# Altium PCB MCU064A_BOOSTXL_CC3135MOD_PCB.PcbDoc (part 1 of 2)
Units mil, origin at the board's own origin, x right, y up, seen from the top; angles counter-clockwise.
Board outline 2300 x 1700 mil, 2 copper layers (Top Layer, Bottom Layer), stack 45.707 mil thick; 110 components, 81 nets, 379 pads, 305 vias.
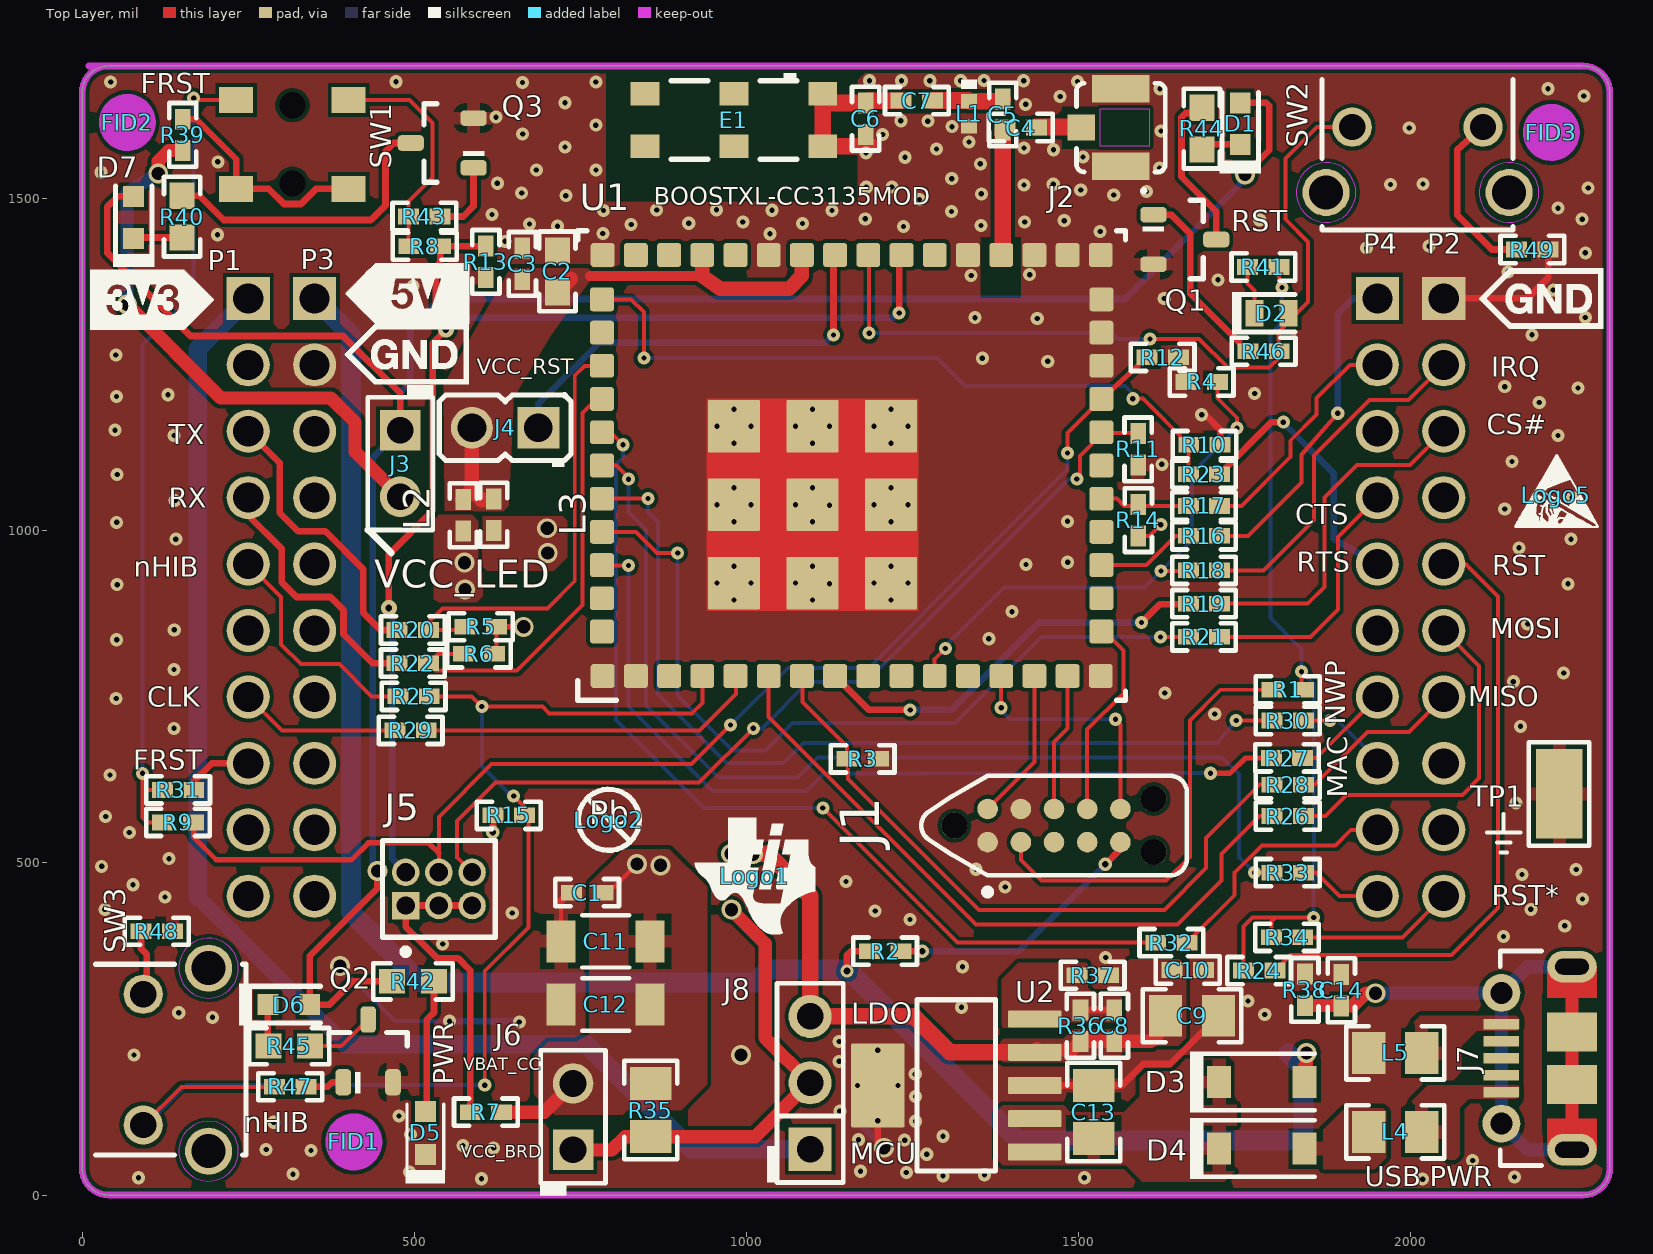
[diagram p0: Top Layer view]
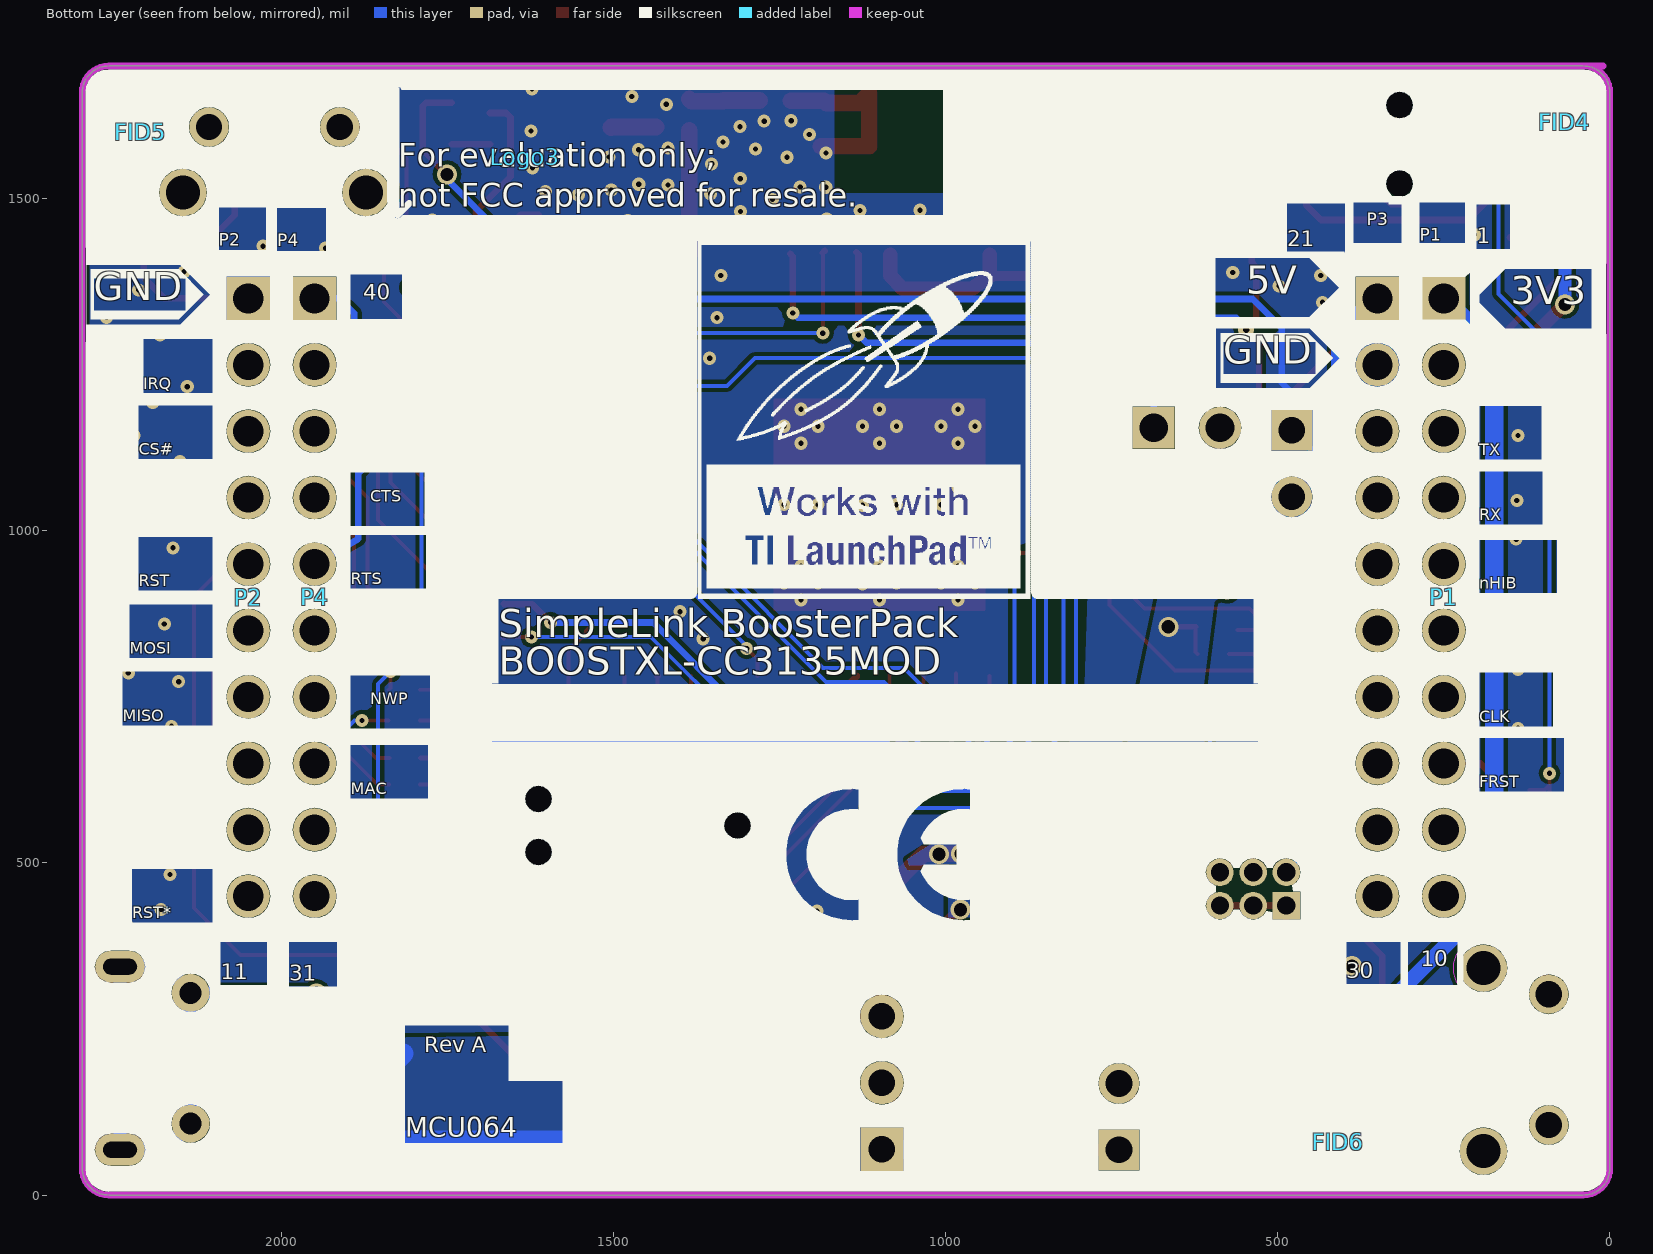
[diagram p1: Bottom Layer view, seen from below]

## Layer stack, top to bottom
Top Solder: solder mask 0.6, Solder Resist, Dk 3.5
Top Layer: signal copper 1.8
Dielectric1: core 42.107, FR-4, Dk 4.8
Bottom Layer: signal copper 1.8
Bottom Solder: solder mask 0.6, Solder Resist, Dk 3.5

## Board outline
0,40 ccw(c40,40) 40,0 2260,0 ccw(c2260,40) 2300,40 2300,1660 ccw(c2260,1660) 2260,1700 40,1700 ccw(c40,1660) 0,1660

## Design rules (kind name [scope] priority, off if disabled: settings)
AcuteAngle [All] p1: minimum=4.50000000000000E+0001 checktracksonly=TRUE
AssemblyTestPointUsage [All] p1: valid=2
Clearance Clearance_8 [InNamedPolygon('NONET_L01_P126')] p1: gap=0 ignorepadtopadclearanceinfootprint=FALSE
Clearance Clearance_7 [InNamedPolygon('NONET_L01_P124')] p2: gap=0 ignorepadtopadclearanceinfootprint=FALSE
Clearance Clearance_6 [InNamedPolygon('NONET_L01_P129')] p3: gap=0 ignorepadtopadclearanceinfootprint=FALSE
Clearance Clearance_5 [InNamedPolygon('NONET_L01_P125')] p4: gap=0 ignorepadtopadclearanceinfootprint=FALSE
Clearance [InNamedPolygon('NONET_L01_P125')] p5: gap=10 ignorepadtopadclearanceinfootprint=FALSE except(0: Arc-Hole Track-Hole SMDPad-Hole THPad-Hole Via-Hole Fill-Hole Poly-Hole Region-Hole Text-Hole)
Clearance Clearance_4 [All] p6: gap=6 ignorepadtopadclearanceinfootprint=FALSE except(0: Arc-Hole Track-Hole SMDPad-Hole THPad-Hole Via-Hole Fill-Hole Poly-Hole Region-Hole Text-Hole)
Clearance Clearance_3 [InNetClass('50 ohm') vs INPOLY] p7: gap=15 ignorepadtopadclearanceinfootprint=FALSE except(0: Arc-Hole Track-Hole SMDPad-Hole THPad-Hole Via-Hole Fill-Hole Poly-Hole Region-Hole Text-Hole)
Clearance Clearance_1 [inpoly vs inpoly] p8: gap=10 ignorepadtopadclearanceinfootprint=FALSE except(0: Arc-Hole Track-Hole SMDPad-Hole THPad-Hole Via-Hole Fill-Hole Poly-Hole Region-Hole Text-Hole)
Clearance Clearance_Poly [InPolygon] p9: gap=8 ignorepadtopadclearanceinfootprint=FALSE except(0: Arc-Hole Track-Hole SMDPad-Hole THPad-Hole Via-Hole Fill-Hole Poly-Hole Region-Hole Text-Hole)
Clearance Clearance_2 [iskeepout] p10: gap=0 ignorepadtopadclearanceinfootprint=FALSE
Clearance Clearance_RF [InNet('NetC5_1') vs InNet('RF_BG')] p11: gap=6 ignorepadtopadclearanceinfootprint=FALSE except(0: Arc-Hole Track-Hole SMDPad-Hole THPad-Hole Via-Hole Fill-Hole Poly-Hole Region-Hole Text-Hole; 6.5: Track-Poly)
Clearance Clearance_RF_1 [InNet('NetC6_2') vs InNet('RF_BG')] p12: gap=6 ignorepadtopadclearanceinfootprint=FALSE except(0: Arc-Hole Track-Hole SMDPad-Hole THPad-Hole Via-Hole Fill-Hole Poly-Hole Region-Hole Text-Hole; 6.5: Track-Poly)
ComponentClearance ComponentClearance_MountingHoles_FiducialMarks [InComponentClass('Mounting Holes') vs InComponentClass('FiducialMark')] p1: gap=10 collisioncheckmode=3 verticalgap=10 showdistances=FALSE
ComponentClearance ComponentClearance_Shunt [InComponentClass('Header') vs InComponentClass('Shunt')] p2: gap=0 collisioncheckmode=3 verticalgap=0 showdistances=FALSE
ComponentClearance ComponentClearance_Logo [InComponentClass('Logo')] p3: gap=0 collisioncheckmode=3 verticalgap=0 showdistances=FALSE
ComponentClearance ComponentClearance_ScrewToNut [(HasFootprint('NY PMS 440 0025 PH')) vs (HasFootprint('Keystone_1902C'))] p4: gap=0 collisioncheckmode=3 verticalgap=0 showdistances=FALSE
ComponentClearance ComponentClearance_MountingHoles [InComponentClass('Mounting Holes')] p5: gap=20 collisioncheckmode=3 verticalgap=100000 showdistances=FALSE
ComponentClearance ComponentClearance_SmallPassives [HasFootprint('0201*') or HasFootprint('0402*') or HasFootprint('0508') or HasFootprint('0603*') or HasFootprint('0612') or HasFootprint('0805*') or HasFootprint('0815*') or HasFootprint('0830*') or HasFootprint('1206*') or HasFootprint('1210*') or HasFootprint('1808*') or HasFootprint('1812*') or HasFootprint('1825*') or HasFootprint('2010*') or HasFootprint('2220*') or HasFootprint('2225*') or HasFootprint('2512*') or HasFootprint('2728*') or HasFootprint('3518*') vs HasFootprint('0201*') or HasFootprint('0402*') or HasFootprint('0508') or HasFootprint('0603*') or HasFootprint('0612') or HasFootprint('0805*') or HasFootprint('0815*') or HasFootprint('0830*') or HasFootprint('1206*') or HasFootprint('1210*') or HasFootprint('1808*') or HasFootprint('1812*') or HasFootprint('1825*') or HasFootprint('2010*') or HasFootprint('2220*') or HasFootprint('2225*') or HasFootprint('2512*') or HasFootprint('2728*') or HasFootprint('3518*')] p6: gap=10 collisioncheckmode=3 verticalgap=10 showdistances=FALSE
ComponentClearance ComponentClearance_THtoSMT [IsThruComponent vs IsSMTComponent] p7: gap=10 collisioncheckmode=3 verticalgap=10 showdistances=FALSE
ComponentClearance ComponentClearance_THtoTH [IsThruComponent vs IsThruComponent] p8: gap=0 collisioncheckmode=3 verticalgap=10 showdistances=FALSE
ComponentClearance [All] p9: gap=10 collisioncheckmode=3 verticalgap=10 showdistances=FALSE
DiffPairsRouting [All] p1: maxlimit=100 minlimit=10 mostfreqgap=10 toplayer_minwidth=15 toplayer_maxwidth=15 toplayer_prefwidth=15 bottomlayer_minwidth=15 bottomlayer_maxwidth=15 bottomlayer_prefwidth=15 maxuncoupledlength=1000
FabricationTestPointUsage TestPointUsage [All] p1: valid=2 allowmultiple=FALSE
FabricationTestpoint Testpoint [All] p1: side=3 testpointundercomponent=TRUE minsize=40 maxsize=100 preferedsize=60 minholesize=0 maxholesize=40 preferedholesize=32 testpointgrid=1 allowsidetop=TRUE allowsidebottom=TRUE usegrid=TRUE gridtolerance=0.01
FanoutControl Fanout_LCC [IsLCC] p1: bgadir=Out bgaviamode=Centered fanoutstyle=Auto fanoutdirection=Alternating viagrid=1 // Fanout_LCC (Default Rule)
FanoutControl Fanout_BGA [IsBGA] p2: bgadir=Out bgaviamode=Centered fanoutstyle=Auto fanoutdirection=Alternating viagrid=1 // Fanout_BGA (Default Rule)
FanoutControl Fanout_Default [All] p4: bgadir=Out bgaviamode=Centered fanoutstyle=Auto fanoutdirection=Alternating viagrid=1 // Fanout_Default (Default Rule)
FanoutControl Fanout_Small [(CompPinCount < 5)] p5: bgadir=Out bgaviamode=Centered fanoutstyle=Auto fanoutdirection=OutThenIn viagrid=1 // Fanout_Small (Default Rule)
Height [All] p1: minheight=0 maxheight=1345 prefheight=500
HoleSize [All] p1: absolutevalues=TRUE maxlimit=251 minlimit=7.86 maxpercent=80.000 minpercent=20.000
MinimumAnnularRing MinimumAnnularRing_ThermalPadVias [IsVia and InAnyComponent] p1: minimumring=5
MinimumAnnularRing [All] p2: minimumring=5
MinimumSolderMaskSliver MinimumSolderMaskSliver_Logo [InComponentClass('Logo') vs InComponentClass('Logo')] p1: minsoldermaskwidth=0.7
MinimumSolderMaskSliver [All] p2: minsoldermaskwidth=3
PlaneConnect [All] p1: planeconnectstyle=Relief reliefexpansion=10 reliefentries=4 reliefconductorwidth=10 reliefairgap=10
PolygonConnect PolygonConnect_3 [InPadClass('SMD')] p1: connectstyle=Relief reliefconductorwidth=20 reliefentries=4 polygonreliefangle="90 Angle" airgapwidth=10
PolygonConnect [InPadClass('TH')] p2: connectstyle=Relief reliefconductorwidth=20 reliefentries=4 polygonreliefangle="90 Angle" airgapwidth=10
PolygonConnect PolygonConnect_1 [InPadClass('PLANECLASS')] p3: connectstyle=Direct reliefconductorwidth=10 reliefentries=4 polygonreliefangle="90 Angle" airgapwidth=10
PolygonConnect PolygonConnect_2 [All] p4: connectstyle=Direct reliefconductorwidth=10 reliefentries=4 polygonreliefangle="90 Angle" airgapwidth=10
RoutingVias ThermalPadVias [IsVia and InAnyComponent] p1: holewidth=7.87 width=24 viastyle="Through Hole" minholewidth=7.87 minwidth=19 maxholewidth=12.99 maxwidth=24
RoutingVias [All] p2: holewidth=16 width=34 viastyle="Through Hole" minholewidth=7.87 minwidth=19 maxholewidth=40 maxwidth=65
SilkToSilkClearance SilkToSilkClearance_Pb-FreeLogo [(HasFootprint('Pb-Free_Overlay_Medium') OR HasFootprint('Pb-Free_Overlay_Small')) vs (HasFootprint('Pb-Free_Overlay_Medium') OR HasFootprint('Pb-Free_Overlay_Small'))] p1: silktosilkclearance=0
SilkToSilkClearance [All] p2: silktosilkclearance=3
SilkToSolderMaskClearance "Silk to Solder Mask Opening" [IsPad] p1: minsilkscreentomaskgap=1 clearancetoexposedcopper=TRUE
SolderMaskExpansion SolderMaskExpansion_1 [InPadClass('SM')] p1: expansion=2.5
SolderMaskExpansion [All] p2: expansion=0
Width [All] p1: maxlimit=40 minlimit=6 preferedwidth=6 checkconnectedcopper=TRUE
15 further rules are at their usual default settings.

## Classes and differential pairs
component class Logo: Logo1
net class Undefined: CC_SPI_CLK CC_SPI_CS CC_SPI_DIN CC_SPI_DOUT CC_UART1_TX GND NetC2_1 NetD4_2 NetJ4_1 SFL_CLK VBAT_CC VCC_LDO_3V3 VCC_LED
net class "50 ohm": NetC4_1 RF_BG
component class BOOSTXL_CC3135MOD_EVMHardware: FID1 FID2 FID3 FID4 FID5 FID6 Logo1 Logo2 Logo3 Logo5
pad class SM: J4-3 J4-4 J4-5 J4-6
component class BOOSTXL_CC3135MOD_HostInterface: C8 C9 C10 C11 C12 C13 C14 D1 D2 D3 D4 D5 D6 D7 J3 J6 J7 J8 L4 L5 P1 P2 P3 P4 Q1 Q2 Q3 R15 R16 R17 R18 R19 R20 R21 R22 R23 R24 R25 R26 R27 R28 R29 R30 R31 R32 R33 R34 R35 R36 R37 R38 R39 R40 R41 R42 R43 R44 R45 R46 R47 R48 R49 SW1 SW2 SW3 TP1 U2
component class BOOSTXL_CC3135MOD_Engine: C1 C2 C3 C4 C5 C6 C7 E1 J1 J2 J4 J5 L1 L2 L3 R1 R2 R3 R4 R5 R6 R7 R8 R9 R10 R11 R12 R13 R14 U1
component class FiducialMark: FID1 FID2 FID3 FID4 FID5 FID6
component class Header: J3 J4 J5 J6 J8
pad class PLANECLASS: J2-1 J2-2 J2-3
pad class SMD: C11-1 C11-2 C13-1 C13-2 C18-1 C18-2 C28-1 C28-2 C29-1 C29-2 C30-1 C30-2 C31-1 C31-2 C32-1 C32-2 D3-1 D3-2 D4-1 D4-2 L7-1 L7-2 L8-1 L8-2 Q1-1 Q1-2 Q1-3 Q2-1 Q2-2 Q2-3 Q3-1 Q3-2 Q3-3 R2-1 R2-2 R5-1 R5-2 R8-1 R8-2 R10-1 R10-2 R11-1 R11-2 R13-1 R13-2 R14-1 R14-2 R15-1 R15-2 R16-1 R16-2 R17-1 R17-2 R18-1 R18-2 R20-1 R20-2 R21-1 R21-2 R22-1 R22-2 R23-1 R23-2 R24-1 R24-2 R25-1 R25-2 R26-1 R26-2 R29-1 R29-2 R31-1 R31-2 R32-1 R32-2 R33-1 R33-2 R39-1 R39-2 R40-1 R40-2 R41-1 R41-2 R42-1 R42-2 R43-1 R43-2 R45-1 R45-2 R46-1 R46-2 R48-1 R48-2 R54-1 R54-2 R56-1 R56-2 R57-1 R57-2 R59-1 R59-2 R60-1 R60-2 R290-1 R290-2 R295-1 R295-2 R297-1 R297-2 TP1-1 U4-6

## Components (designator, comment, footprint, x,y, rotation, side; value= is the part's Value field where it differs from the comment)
C1 "GRM155R60J475ME47D" 0402 760.2,455.3 r180 top locked value=4.7uF
C2 "GRM188R60J106ME47D" 0603 715.5,1390.7 r90 top locked value=10uF
C3 "GRM155R60J104KA01D" 0402 662.7,1402.1 r90 top locked value=0.1uF
C4 "500R07S100JV4T" 0402 1413.1,1607.3 r180 top value=10pF
C5 "500R07S100JV4T" 0402 1386,1626.87 r90 top value=10pF
C6 "GRM1555C1H1R8CA01D" 0402 1179.6,1620.69 r270 top value=1.8pF
C7 "GJM1555C1H3R3BB01D" 0402 1256.62,1647.9 r0 top value=3.3pF
C8 "GRM1555C1H150JA01D" 0402 1554,255 r90 top locked value=15pF
C9 "GRM21BR61A106KE19L" 0805_HV 1671,270 r0 top locked value=10uF
C10 "GRM155R60J104KA01D" 0402 1664.5,338.8 r0 top value=0.1uF
C11 "GRM31CR60J107ME39L" 1206_180 788,382 r180 top locked value=100uF
C12 "GRM31CR60J107ME39L" 1206_180 788,287 r180 top locked value=100uF
C13 "GRM21BR61A106KE19L" 0805_HV 1523,125 r90 top locked value=10uF
C14 "GRM155R71H102KA01D" 0402 1895.8,308.3 r90 top locked value=1000pF
D1 "150060YS75000" WL-SMCW_YELLOW 1743.6,1613 r90 top locked value=Yellow
D2 "CD0603-B00340" Diode_0603 1790.51,1327.6 r0 top locked value=45V
D3 "MBR130T1G" SOD-123 1776,170 r0 top locked value=30V
D4 "MBR130T1G" SOD-123 1776,70 r0 top locked value=30V
D5 "SML-311UTT86" SML-31_Red 516.6,93.5 r90 top locked value=Red
D6 "150060GS75000" WL-SMCW_GREEN 311.1,286.8 r0 top locked value=Green
D7 "150060RS75000" WL-SMCW_RED 77.5,1472 r90 top locked value=Red
E1 "M830520" Ethertronics_M830520 981.3,1618.52 r270 top locked
FID1 "Fiducial" Fiducial6.4-20 409,80 r90 top locked
FID2 "Fiducial" Fiducial6.4-20 68,1615 r90 top locked
FID3 "Fiducial" Fiducial6.4-20 2212,1600 r90 top locked
FID4 "Fiducial" Fiducial6.4-20 68,1615 r90 bottom locked
FID5 "Fiducial" Fiducial6.4-20 2212,1600 r90 bottom
FID6 "Fiducial" Fiducial6.4-20 409,80 r90 bottom locked
J1 "TC2050-IDC-430-FP" Tag_TC2050-NL 1463.2,556.3 r90 top locked
J2 "U.FL-R-SMT-1" CONN_UFL-R-SMT-1 1563.9,1607.3 r0 top locked
J3 "HMTSW-102-07-G-S-240" SAMTEC_HMTSW-102-07-G-S-240 478.8,1101.3 r270 top locked
J4 "961102-6404-AR" 3M_961102-6404-AR 636.8,1155.2 r180 top locked
J5 "GRPB032VWVN-RC" Sullins_GRPB032VWVN-RC 537,460.9 r90 top locked
J6 "HMTSW-102-07-G-S-240" SAMTEC_HMTSW-102-07-G-S-240 739,118 r90 top locked
J7 "105017-0001" CONN_105017-0001 2189.93,206 r90 top locked
J8 "TSW-103-07-G-S" TSW-103-07-G-S 1096,169 r90 top locked
L1 "LQG15HS3N0S02D" IND_LQG15H 1335.3,1628.2 r270 top value=3nH
L2 "BLM15AX100SN1D" 0402 573.8,1023.5 r270 top locked value="10 ohm"
L3 "BLM15AX100SN1D" 0402 619.5,1024.3 r270 top locked value="10 ohm"
L4 "MMZ2012R300A" 0805_HV 1977,95 r180 top locked value="30 ohm"
L5 "MMZ2012R300A" 0805_HV 1977,214 r0 top locked value="30 ohm"
Logo1 "Texas Instruments" TI_Symbol_Overlay_Small 1012.9,480.1 r0 top
Logo2 "Pb-Free Symbol" Pb-Free_Overlay_Small 792.9,565 r0 top
Logo3 "FCC disclaimer" FCC_disclaimer 1633,1563 r180 bottom
Logo5 "ESD Susceptible" ESD_Overlay_Small 2219.1,1053.9 r0 top
P1 "SSW-110-23-F-S" CONN_SSW-110-23-F-S 250,900 r90 bottom locked
P2 "SSW-110-23-F-S" CONN_SSW-110-23-F-S 2050,900 r90 bottom locked
P3 "SSW-110-23-F-S" CONN_SSW-110-23-F-S 350,900 r90 bottom locked
P4 "SSW-110-23-F-S" CONN_SSW-110-23-F-S 1950,900 r90 bottom locked
Q1 "BSS138" SOT-23 1660.2,1438.7 r0 top locked value=50V
Q2 "BSS138" SOT-23 430.5,217.1 r90 top locked value=50V
Q3 "BSS138" SOT-23 542,1584 r180 top locked value=50V
R1 "ERJ-2GE0R00X" 0402 1815.1,760.8 r0 top locked value=0
R2 "ERJ-2GE0R00X" 0402 1209,367.2 r0 top locked value=0
R3 "CRCW0402100KJNED" 0402 1175,656.8 r0 top locked value=100k
R4 "CRCW0402100KJNED" 0402 1685.5,1224.2 r180 top locked value=100k
R5 "CRCW0402100KJNED" 0402 600,855.7 r180 top locked value=100k
R6 "CRCW0402100KJNED" 0402 597.3,814.9 r180 top locked value=100k
R7 "CRCW04021K00JNED" 0402 607.9,124.9 r180 top locked value=1.0k
R8 "ERJ-2GE0R00X" 0402 515.7,1428.6 r180 top locked value=0
R9 "ERJ-2GE0R00X" 0402 144.2,561 r180 top locked value=0
R10 "CRCW0402100KJNED" 0402 1689.7,1129.9 r0 top locked value=100k
R11 "CRCW0402100KJNED" 0402 1589.8,1122.8 r270 top locked value=100k
R12 "CRCW0402100KJNED" 0402 1626.8,1261.2 r0 top locked value=100k
R13 "CRCW0402100KJNED" 0402 607.7,1405.1 r270 top locked value=100k
R14 "CRCW0402100KJNED" 0402 1590.2,1016.1 r90 top locked value=100k
R15 "CRCW0402100KFKED" 0402 642.2,571.7 r180 top locked value=100k
R16 "ERJ-2GE0R00X" 0402 1689,992.5 r0 top locked value=0
R17 "ERJ-2GE0R00X" 0402 1689,1037.5 r0 top locked value=0
R18 "ERJ-2GE0R00X" 0402 1689,940.5 r180 top locked value=0
R19 "ERJ-2GE0R00X" 0402 1689,890.5 r180 top locked value=0
R20 "ERJ-2GE0R00X" 0402 497.9,850.8 r180 top locked value=0
R21 "ERJ-2GE0R00X" 0402 1689,840.5 r0 top locked value=0
R22 "ERJ-2GE0R00X" 0402 497.9,800.8 r180 top locked value=0
R23 "ERJ-2GE0R00X" 0402 1689,1085.5 r0 top locked value=0
R24 "ERJ-2GE0R00X" 0402 1772,338 r180 top locked value=0
R25 "CRCW04021K00JNED" 0402 498.9,750.8 r180 top locked value=1.0k
R26 "ERJ-2GE0R00X" 0402 1815.1,570.7 r180 top locked value=0
R27 "ERJ-2GE0R00X" 0402 1814,658 r0 top locked value=0
R28 "ERJ-2GE0R00X" 0402 1815.1,617.8 r180 top locked value=0
R29 "ERJ-2GE0R00X" 0402 494.4,699.7 r180 top locked value=0
R30 "ERJ-2GE0R00X" 0402 1815.1,714.5 r0 top locked value=0
R31 "CRCW04021K00JNED" 0402 144.38,610 r0 top locked value=1.0k
R32 "ERJ-2GE0R00X" 0402 1640,380 r0 top locked value=0
R33 "ERJ-2GE0R00X" 0402 1815.1,485.4 r0 top locked value=0
R34 "ERJ-2GE0R00X" 0402 1814,388 r180 top locked value=0
R35 "CRM0805-FX-R100ELF" 0805_HV 856,128 r90 top locked value=0.1
R36 "CRCW040251K0JNED" 0402 1503,255 r270 top locked value=51k
R37 "CRCW040230K1FKED" 0402 1521.29,330.95 r180 top locked value=30.1k
R38 "CRCW0402100KJNED" 0402 1841,309 r90 top locked value=100k
R39 "ERJ-2RKF1000X" 0402 151.4,1596.2 r270 top locked value=100
R40 "RC0603JR-07750RL" 0603 150.3,1473.2 r270 top value=750
R41 "ERJ-2GE0R00X" 0402 1778.38,1397.3 r0 top locked value=0
R42 "RC0603JR-07750RL" 0603 498.1,321.8 r180 top value=750
R43 "CRCW040210K0JNED" 0402 515.1,1473.4 r0 top locked value=10k
R44 "RC0603JR-07750RL" 0603 1685.9,1605.6 r270 top locked value=750
R45 "RC0603JR-07750RL" 0603 311.75,224.23 r180 top value=750
R46 "CRCW040210K0JNED" 0402 1778.7,1270.4 r180 top locked value=10k
R47 "CRCW040210K0JNED" 0402 313.2,163 r0 top locked value=10k
R48 "ERJ-2RKF1000X" 0402 112.2,397.2 r180 top locked value=100
R49 "ERJ-2RKF1000X" 0402 2183.46,1423.66 r180 top locked value=100
SW1 "EVQ-PSD02K" SW_EVQ-PSD02K 316.5,1581.9 r90 top locked
SW2 "MJTP1117" SW_MJTP1117 2010.54,1685.47 r180 top
SW3 "MJTP1117" SW_MJTP1117 14.3,203.87 r270 top
TP1 "5015" Testpoint_Keystone_Miniature 2224.1,604 r270 top locked
U1 "CC3135MODRNMMOBR" MOB0063A 1158.6,1098.5 r90 top locked
U2 "TPS79601DCQR" DCQ0006A 1316,165 r180 top locked
ZZ2 "These assemblies are ESD sensitive, ESD precautions shall be observed." AssemblyNote 232.1,2266.9 r0 top
ZZ3 "These assemblies must be clean and free from flux and all contaminants. Use of no clean flux is not acceptable." AssemblyNote 232.1,2148.7 r0 top
ZZ4 "These assemblies must comply with workmanship standards IPC-A-610 Class 2, unless otherwise specified." AssemblyNote 232.1,2039.8 r0 top

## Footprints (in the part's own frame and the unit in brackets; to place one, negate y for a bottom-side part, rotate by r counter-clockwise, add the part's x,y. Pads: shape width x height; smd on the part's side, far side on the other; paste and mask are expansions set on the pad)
3M_961102-6404-AR [mm] "Header, 2.54mm, 2x1, TH"
  rect 1.6x1.6 hole 1.1: 1(-1.27,0)
  round 1.6 hole 1.1: 2(1.27,0)
  silkscreen extent -2.52,-1.25 2.52,1.5, body extent -2.52,-1.25 2.52,1.25, height 8.5
0402 [mm] "0402 from SM-752 data"
  rect 0.8x0.6 smd: 1(-0.6,0) 2(0.6,0)
  silkscreen extent -1.22,-0.52 1.22,0.52, body extent -0.55,-0.3 0.55,0.3, height 0.6
0603 [mm] "0603 from SM-752 data"
  rect 1x0.95 smd: 1(-0.8,0) 2(0.8,0)
  silkscreen extent -1.52,-0.69 1.52,0.69, body extent -0.87,-0.47 0.87,0.47, height 1
0805_HV [mil] "0805 with 30mil clearance between pads"
  rect 50x63 smd: 1(-40,0) 2(40,0)
  silkscreen extent -74,-40 74,40, body extent -43,-29 43,29, height 57
1206_180 [mm] "1206_180"
  rect 1.1x1.6 smd: 1(-1.7,0) 2(1.7,0)
  silkscreen extent -0.9,-1 0.9,1, body extent -1.75,-0.95 1.75,0.95, height 1.8
AssemblyNote [mil] "Assembly Note"
CONN_105017-0001 [mm] "Molex Micro USB-B"
  rect 0.4x1.35 smd: 1(-1.3,1.35) 2(-0.65,1.35) 3(0,1.35) 4(0.65,1.35) 5(1.3,1.35)
  oval 1.2x1.9 hole 0.6 slot 1.3 at 90 deg: 6(-3.5,-1.35) 9(3.5,-1.35)
  rect 1.5x1.9 smd: 7(-1,-1.35) 8(1,-1.35)
  round 1.45 hole 0.85: 10(2.5,1.35) 11(-2.5,1.35)
  Top Layer region: 3.5,-0.4 2.3,-0.4 2.3,-2.3 3.5,-2.3
  Top Layer region: -3.5,-2.3 -2.3,-2.3 -2.3,-0.4 -3.5,-0.4
  silkscreen extent -4.1,-0.2 4.1,1.4, body extent -4.1,-3.93 4.1,1.5, height 2.72
CONN_SSW-110-23-F-S [mm] "SAMTEC"
  rect 1.65x1.65 hole 1.15: 1(11.43,0)
  round 1.65 hole 1.15: 2(8.89,0) 3(6.35,0) 4(3.81,0) 5(1.27,0) 6(-1.27,0) 7(-3.81,0) 8(-6.35,0) 9(-8.89,0) 10(-11.43,0)
  silkscreen extent -13.08,-1.27 13.08,1.27, body extent -13,-1.27 13,1.27, height 8.59
CONN_UFL-R-SMT-1 [mm] "Hirose recommended land pattern http://www.hirose.co.jp/cataloge_hp/e32119372.pdf 2009.2"
  rect 1.05x1 smd paste-0.1 mask-0.1: 1(-1.525,0)
  rect 2.2x1.05 smd paste-2 mask-2: 2(0,1.475) 3(0,-1.475)
  rect 2x0.9 on Top Paste: 2(0,1.5) 3(0,-1.5)
  rect 2x0.9 on Top Solder: 2(0,1.5) 3(0,-1.5)
  Top Layer keep-out region: -0.8,-0.7 1.1,-0.7 1.1,0.7 -0.8,0.7
  silkscreen extent -1.7,-1.7 1.7,1.7, body extent -1.55,-1.5 1.55,1.5, height 1.27
DCQ0006A [mm] "SOT223, 6-Leads, Body 6.6x7.3mm (max), Pitch 1.27mm"
  rrect15% 2.05x0.65 smd: 1(-3,2.54) 2(-3,1.27) 3(-3,0) 4(-3,-1.27) 5(-3,-2.54)
  rrect11% 0.92x1.31 on Top Paste: 6(2.44,-0.755) 6(2.44,0.755) 6(3.56,-0.755) 6(3.56,0.755)
  rrect5% 2.05x3.2 smd paste-2: 6(3,0)
  silkscreen extent -1.5,-3.27 1.5,3.27, body extent -3.54,-3.25 3.54,3.25, height 1.8
Diode_0603 [mm] "Based on Bourns recommended land pattern Rev 10/09"
  rect 0.7x1 smd: 1(-0.65,0) 2(0.65,0)
  silkscreen extent -1.5,-0.8 0.9,0.8, body extent -0.9,-0.5 0.9,0.5, height 0.85
ESD_Overlay_Small [mil]
  silkscreen extent -62,-48 64,61
Ethertronics_M830520 [mm] "SMD, 6-Leads, Body 8x3mm"
  rect 0.9x1.1 smd: 1(-1,3.4) 2(1,3.4) 3(1,0) 4(1,-3.4) 5(-1,-3.4) 6(-1,0)
  silkscreen extent -1.8,-2.4 1.5,2.4, body extent -1.5,-4 1.5,4, height 1.33
FCC_disclaimer [mil]
Fiducial6.4-20 [mil]
  round 25 smd mask+26.87: 1(0,0)
  Top Layer keep-out circle w46.37: c0,0 r19.68
IND_LQG15H [mm] "MuRata"
  rect 0.55x0.6 smd: 1(-0.475,0) 2(0.475,0)
  silkscreen extent -1.3,-0.3 -0.95,0.3, body extent -0.52,-0.27 0.52,0.27, height 0.55
MOB0063A [mm]
  rrect22% 0.91x0.91 smd paste-0.05 mask-0.05: 1(-8.05,9.525) 2(-8.05,8.255) 3(-8.05,6.985) 4(-8.05,5.715) 5(-8.05,4.445) 6(-8.05,3.175) 7(-8.05,1.905) 8(-8.05,0.635) 9(-8.05,-0.635) 10(-8.05,-1.905) 11(-8.05,-3.175) 12(-8.05,-4.445) 13(-8.05,-5.715) 14(-8.05,-6.985) 15(-8.05,-8.255) 16(-8.05,-9.525) 17(-6.35,-9.55) 18(-5.08,-9.55) 19(-3.81,-9.55) 20(-2.54,-9.55) 21(-1.27,-9.55) 22(0,-9.55) 23(1.27,-9.55) 24(2.54,-9.55) 25(3.81,-9.55) 26(5.08,-9.55) 27(6.35,-9.55) 28(8.05,-9.525) 29(8.05,-8.255) 30(8.05,-6.985) 31(8.05,-5.715) 32(8.05,-4.445) 33(8.05,-3.175) 34(8.05,-1.905) 35(8.05,-0.635) 36(8.05,0.635) 37(8.05,1.905) 38(8.05,3.175) 39(8.05,4.445) 40(8.05,5.715) 41(8.05,6.985) 42(8.05,8.255) 43(8.05,9.525) 44(6.35,9.55) 45(5.08,9.55) 46(3.81,9.55) 47(2.54,9.55) 48(1.27,9.55) 49(0,9.55) 50(-1.27,9.55) 51(-2.54,9.55) 52(-3.81,9.55) 53(-5.08,9.55) 54(-6.35,9.55)
  rrect11% 0.89x0.89 on Top Paste: 55(-5.05,3.95) 55(-3.95,3.95) 56(-5.05,0.95) 56(-5.05,2.05) 56(-3.95,0.95) 56(-3.95,2.05) 57(-5.05,-2.05) 57(-5.05,-0.95) 57(-3.95,-2.05) 57(-3.95,-0.95) 58(-2.05,3.95) 58(-2.05,5.05) 58(-0.95,5.05) 58(-0.95,3.95) 59(-2.05,0.95) 59(-2.05,2.05) 59(-0.95,2.05) 59(-0.95,0.95) 60(-2.05,-2.05) 60(-2.05,-0.95) 60(-0.95,-0.95) 60(-0.95,-2.05) 61(0.95,5.05) 61(0.95,3.95) 61(2.05,3.95) 61(2.05,5.05) 62(0.95,2.05) 62(0.95,0.95) 62(2.05,0.95) 62(2.05,2.05) 63(0.95,-0.95) 63(0.95,-2.05) 63(2.05,-2.05) 63(2.05,-0.95)
  rrect5% 2x2 smd paste-1 mask-1: 55(-4.5,4.5)
  rrect5% 2x2 smd paste-1 mask+0: 56(-4.5,1.5) 57(-4.5,-1.5) 58(-1.5,4.5) 59(-1.5,1.5) 60(-1.5,-1.5) 61(1.5,4.5) 62(1.5,1.5) 63(1.5,-1.5)
  Top Layer region: -5.55,-2.5 -5.55,5.5 -5.546,5.519 -5.535,5.535 -5.519,5.546 -5.5,5.55 -5.5,5.55 2.5,5.55 2.519,5.546 2.535,5.535 2.546,5.519 2.55,5.5 2.55,5.5 2.55,-2.5 2.546,-2.519 2.535,-2.535 2.519,-2.546 2.5,-2.55 2.5,-2.55 -5.5,-2.55 -5.519,-2.546 -5.535,-2.535 -5.546,-2.519 -5.55,-2.5
  silkscreen extent -8.97,-10.48 8.98,10.48, body extent -8.75,-10.25 8.75,10.25, height 2.45
Pb-Free_Overlay_Small [mil]
  silkscreen extent -46,-46 46,46
SAMTEC_HMTSW-102-07-G-S-240 [mm] "Header, 2.54mm, 2x1, TH"
  rect 1.55x1.55 hole 1.02: 1(-1.27,0)
  round 1.55 hole 1.02: 2(1.27,0)
  silkscreen extent -3.01,-1.24 2.54,1.27, body extent -2.54,-1.27 2.54,1.27, height 8.64
SML-31_Red [mm] "Rohm"
  rect 0.8x0.8 smd: 1(-0.825,0) 2(0.825,0)
  silkscreen extent -1.93,-0.76 1.1,0.76, body extent -0.85,-0.45 0.85,0.45, height 0.91
SOD-123 [mm] "On Semi recommended land pattern"
  rect 0.915x1.22 smd: 1(-1.637,0) 2(1.637,0)
  silkscreen extent -2.74,-1.17 2.03,1.17, body extent -1.93,-0.9 1.93,0.9, height 1.35
SOT-23 [mm] "SOT23, 3-Leads, Body 2.9x1.3mm, Pitch 0.95mm, Lead Span 2.5mm, IPC Medium Density"
  rrect50% 1x0.6 smd: 1(-1.2,0.95) 2(-1.2,-0.95) 3(1.2,0)
  silkscreen extent -1.63,-1.5 0.7,1.5, body extent -1.16,-1.45 1.21,1.45, height 1
Sullins_GRPB032VWVN-RC [mm] "Sullins"
  rect 1.05x1.05 hole 0.7 paste+0: 1(-0.635,1.27)
  round 1.05 hole 0.7 paste+0: 2(0.635,1.27) 3(-0.635,0) 4(0.635,0) 5(-0.635,-1.27) 6(0.635,-1.27)
  silkscreen extent -2.51,-2.15 1.85,2.15, body extent -1.85,-2.15 1.85,2.15, height 4
SW_EVQ-PSD02K [mm] "Panasonic"
  rect 1x1.3 smd: 1(-1.7,2.15) 2(-1.7,-2.15) 3(1.7,-2.15) 4(1.7,2.15)
  round 0.5 hole 1 unplated: MH1(-1.5,0) MH2(1.5,0)
  body extent -3.05,-2.3 4.35,2.3, height 1.8
SW_MJTP1117 [mm] "TH, 2-Leads, Body 7.3x5.9mm, Pitch 5mm"
  round 1.5 hole 1: 1(-2.5,1.97) 2(2.5,1.97)
  round 1.8 hole 1.3: MH1(-3.5,4.47) MH2(3.5,4.47)
  silkscreen extent -3.65,0.15 3.65,5.9, body extent -3.95,-1.45 3.95,5.9, height 4.3
Tag_TC2050-NL [mil] "Footprint for Tag-Connect TC2050 No-Legs cables"
  round 31 smd paste-15.75: 1(-25,100) 2(-25,50) 3(-25,0) 4(-25,-50) 5(-25,-100) 6(25,-100) 7(25,-50) 8(25,0) 9(25,50) 10(25,100)
  round 39 hole 39 unplated: MH1(0,150) MH2(-40,-150) MH3(40,-150)
  silkscreen extent -105,-200 75,200
Testpoint_Keystone_Miniature [mil] "Miniature SMT test point"
  rect 135x70 smd: 1(0,0)
  silkscreen extent -78,-46 78,45, body extent -52,-20 52,20, height 61
TI_Symbol_Overlay_Small [mil]
  silkscreen extent -90,-88 91,88
TSW-103-07-G-S [mm] "Samtec 100mil, 1x3, 230 mil above insulator"
  rect 1.65x1.65 hole 1.016: 1(-2.54,0)
  round 1.65 hole 1.016: 2(0,0) 3(2.54,0)
  silkscreen extent -3.81,-1.27 3.81,1.65, body extent -3.81,-1.27 3.81,1.27, height 8.38
WL-SMCW_GREEN [mm] "WURTH"
  rect 0.8x0.8 smd: 1(-0.8,0) 2(0.8,0)
  silkscreen extent -1.9,-0.8 1.2,0.8, body extent -0.85,-0.45 0.85,0.45, height 0.8
WL-SMCW_RED [mm] "WURTH"
  rect 0.8x0.8 smd: 1(-0.8,0) 2(0.8,0)
  silkscreen extent -1.9,-0.8 1.2,0.8, body extent -0.85,-0.45 0.85,0.45, height 0.8
WL-SMCW_YELLOW [mm] "WURTH"
  rect 0.8x0.8 smd: 1(-0.8,0) 2(0.8,0)
  silkscreen extent -1.9,-0.8 1.2,0.8, body extent -0.85,-0.45 0.85,0.45, height 0.8

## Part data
C1: "CAP, CERM, 4.7 µF, 6.3 V, +/- 20%, X5R, 0402", Cap_Case=0402, Manufacturer=MuRata, Supplier Part Number 1=490-5915-1-ND, TempCo=X5R, Tolerance_%=20, Value1=Unknown, Value2=6.3V, ValueDisplayed=4.7µF
C2: "CAP, CERM, 10 µF, 6.3 V, +/- 20%, X5R, 0603", Cap_Case=0603, Manufacturer=MuRata, Supplier Part Number 1=490-3896-1-ND, TempCo=X5R, Tolerance_%=20, Value1="0.009 ohm", Value2=6.3V, ValueDisplayed=10µF
C3 C10: "CAP, CERM, 0.1 µF, 6.3 V, +/- 10%, X5R, 0402", Cap_Case=0402, Manufacturer=MuRata, Supplier Part Number 1=GRM155R60J104KA01D-ND, TempCo=X5R, Tolerance_%=10, Value1=Unknown, Value2=6.3V, ValueDisplayed=0.1µF
C4: "CAP, CERM, 10 pF, 50 V, +/- 5%, C0G/NP0, 0402", Cap_Case=0402, Manufacturer="Johanson Technology", TempCo=C0G/NP0, Tolerance_%=5, Value1=Unknown, Value2=50V, ValueDisplayed=DNP
C5: "CAP, CERM, 10 pF, 50 V, +/- 5%, C0G/NP0, 0402", Cap_Case=0402, Manufacturer="Johanson Technology", TempCo=C0G/NP0, Tolerance_%=5, Value1=Unknown, Value2=50V, ValueDisplayed=10pF
C6: "CAP, CERM, 1.8 pF, 50 V, +/- 5%, C0G/NP0, 0402", Cap_Case=0402, Manufacturer=MuRata, Supplier Part Number 1=14T3291, TempCo=C0G/NP0, Tolerance_%=5, Value1=Unknown, Value2=50V, ValueDisplayed=DNP
C7: library part CMP-0006462-1, "CAP, CERM, 3.3 pF, 50 V, +/- 0.1pF, C0G/NP0, 0402", Cap_Case=0402, Manufacturer=MuRata, Supplier Part Number 1=81-GJM1555C1H3R3BB01, TempCo=C0G/NP0, Tolerance_%=0.1pF, Value1=Unknown, Value2=50V, ValueDisplayed=3.3pF
C8: "CAP, CERM, 15 pF, 50 V, +/- 5%, C0G/NP0, 0402", Cap_Case=0402, Manufacturer=MuRata, Supplier Part Number 1=81-GRM1555C1H150JA1D, TempCo=C0G/NP0, Tolerance_%=5, Value1=Unknown, Value2=50V, ValueDisplayed=15pF
C9 C13: "CAP, CERM, 10 µF, 10 V, +/- 10%, X5R, 0805", Cap_Case=0805, Manufacturer=MuRata, Supplier Part Number 1=490-1709-1-ND, TempCo=X5R, Tolerance_%=10, Value1="0.002 ohm", Value2=10V, ValueDisplayed=10µF
C11 C12: "CAP, CERM, 100 µF, 6.3 V, +/- 20%, X5R, 1206", Cap_Case=1206, Manufacturer=MuRata, Supplier Part Number 1=490-4539-1-ND, TempCo=X5R, Tolerance_%=20, Value1="0.003 ohm", Value2=6.3V, ValueDisplayed=100µF
C14: "CAP, CERM, 1000 pF, 50 V, +/- 10%, X7R, 0402", Cap_Case=0402, Manufacturer=MuRata, Supplier Part Number 1=490-1303-1-ND, TempCo=X7R, Tolerance_%=10, Value1=Unknown, Value2=50V, ValueDisplayed=1000pF
D1: "LED, Yellow, SMD", Color=yellow, Manufacturer="Wurth Elektronik", Supplier Part Number 1=732-4981-1-ND, Value1=W, Value2=2V
D2: "Diode, Schottky, 45 V, 0.03 A, 0603 Diode", Manufacturer=Bourns, Supplier Part Number 1=652-CD0603-B00340, Value1=0.03A, Value2=0.37V
D3 D4: "Diode, Schottky, 30 V, 1 A, SOD-123", Manufacturer="ON Semiconductor", Supplier Part Number 1=MBR130T1GOSCT-ND, Value1=1A, Value2=0.47V
D5: "LED, Red, SMD", Color=red, Manufacturer=Rohm, Supplier Part Number 1=511-1304-1-ND, Value1=W, Value2=1.8V
D6: "LED, Green, SMD", Color=Green, Manufacturer="Wurth Elektronik", Supplier Part Number 1=732-4971-1-ND, Value1=W, Value2=3.2V
D7: "LED, Red, SMD", Color=Red, Manufacturer="Wurth Elektronik", Power_TotalModule=0.072, Supplier Part Number 1=732-4978-1-ND, Value1=0.072W, Value2=2V
E1: library part CMP-0001857-1, "WLAN ANTENNA 802.11, SMD", Manufacturer=Ethertronics
FID1 FID2 FID3 FID4 FID5 FID6: "Fiducial mark.  There is nothing to buy or mount.", Manufacturer=N/A
J1: "Footprint for TC2050-IDC-430", Manufacturer=Tag-Connect
J2: "Connector, Ultra-Mini Coaxial, SMD", Manufacturer="Hirose Electric Co. Ltd.", Supplier Part Number 1=H11891CT-ND
J3 J6: "Header, 100mil, 2x1, Gold, TH", Manufacturer=Samtec, Supplier Part Number 1=HMTSW-102-07-G-S-240-ND
J4: "Header, 2.54mm, 2x1, TH", Color=Black, Current_A=2, Manufacturer=3M, Supplier Part Number 1=3M9447-ND, Voltage_V=1000
J5: "Header, 50mil, 3x2, Gold, TH", Manufacturer="Sullins Connector Solutions", Supplier Part Number 1=S9015E-03-ND
J7: "Connector, Receptacle, Micro-USB Type B, R/A, Bottom Mount SMT", Manufacturer=Molex, Supplier Part Number 1=WM1399CT-ND
J8: "Header, 100mil, 3x1, Gold, TH", Color=Black, Current_A=6.3, Manufacturer=Samtec, Supplier Part Number 1=SAM1029-03-ND, Voltage_V=550
L1: library part CMP-0058630-1, "Inductor, Multilayer, Air Core, 3 nH, 0.3 A, 0.17 ohm, SMD", Manufacturer=MuRata, Supplier Part Number 1=490-6570-1-ND, Value1="0.17 ohm", Value2=0.3A, ValueDisplayed=3nH
L2 L3: "Ferrite Bead, 10 ohm @ 100 MHz, 1.74 A, 0402", Manufacturer=MuRata, Supplier Part Number 1=490-5437-6-ND, Value1="0.015 ohm", Value2=1.74A, ValueDisplayed="10 ohm"
L4 L5: "Ferrite Bead, 30 ohm @ 100 MHz, 1.5 A, 0805", Manufacturer=TDK, Supplier Part Number 1=445-2199-1-ND, Value1="0.05 ohm", Value2=1.5A, ValueDisplayed="30 ohm"
Logo1: library part TI_Logo, "Texas Instrument Corporate Signature"
Logo2: library part Pb-Free
Logo3: library part FCC_disclaimer, "FCC_disclaimer"
Logo5: library part ESD_Susceptible, "ESD Susceptible Symbol"
P1 P2 P3 P4: "Connector, Receptacle, 100mil, 10x1, Gold plated, TH", Manufacturer=Samtec
Q1 Q2 Q3: "MOSFET, N-CH, 50 V, 0.22 A, SOT-23", Alternate Manufacturer=None, Manufacturer="Fairchild Semiconductor", Supplier Part Number 1=BSS138CT-ND, Value1="6 ohm", Value2="1.7 nC"
R1 R2 R8 R9 R18 R19 R20 R21 R22 R23 R24 R26 R27 R28 R29 R30 R41: "RES, 0, 5%, 0.063 W, 0402", Manufacturer=Panasonic, Power_W=0.063, Supplier Part Number 1=P0.0JCT-ND, TempCo="600 ppm/C", Tolerance_%=5, Value1=5%, Value2=0.063W, Value_Code=0000, ValueDisplayed=0
R3 R4 R5 R6 R10 R11 R12 R13 R14: "RES, 100 k, 5%, 0.063 W, 0402", Manufacturer=Vishay-Dale, Power_W=0.063, Supplier Part Number 1=541-100KJCT-ND, TempCo="200 ppm/C", Tolerance_%=5, Value1=5%, Value2=0.063W, Value_Code=100k, ValueDisplayed=DNP
R7 R25 R31: "RES, 1.0 k, 5%, 0.063 W, 0402", Manufacturer=Vishay-Dale, Power_W=0.063, Supplier Part Number 1=541-1.0KJCT-ND, TempCo="200 ppm/C", Tolerance_%=5, Value1=5%, Value2=0.063W, Value_Code=1k00, ValueDisplayed=1.0k
R15: "RES, 100 k, 1%, 0.063 W, 0402", Manufacturer=Vishay-Dale, Power_W=0.063, Supplier Part Number 1=541-100KLCT-ND, TempCo="100 ppm/C", Tolerance_%=1, Value1=1%, Value2=0.063W, Value_Code=100k
R16 R17 R32 R33 R34: "RES, 0, 5%, 0.063 W, 0402", Manufacturer=Panasonic, Power_W=0.063, Supplier Part Number 1=P0.0JCT-ND, TempCo="600 ppm/C", Tolerance_%=5, Value1=5%, Value2=0.063W, Value_Code=0000, ValueDisplayed=DNP
R35: "RES, 0.1, 1%, 0.25 W, 0805", Manufacturer=Bourns, Power_W=0.25, Supplier Part Number 1=652-CRM0805FXR100ELF, TempCo="150 ppm/C", Tolerance_%=1, Value1=1%, Value2=0.25W, Value_Code=R100, ValueDisplayed=DNP
R36: "RES, 51 k, 5%, 0.063 W, 0402", Manufacturer=Vishay-Dale, Power_W=0.063, Supplier Part Number 1=541-51KJCT-ND, TempCo="200 ppm/C", Tolerance_%=5, Value1=5%, Value2=0.063W, Value_Code=51k0, ValueDisplayed=51k
R37: "RES, 30.1 k, 1%, 0.063 W, 0402", Manufacturer=Vishay-Dale, Power_W=0.063, Supplier Part Number 1=541-30.1KLCT-ND, TempCo="100 ppm/C", Tolerance_%=1, Value1=1%, Value2=0.063W, Value_Code=30k1, ValueDisplayed=30.1k
R38: "RES, 100 k, 5%, 0.063 W, 0402", Manufacturer=Vishay-Dale, Power_W=0.063, Supplier Part Number 1=541-100KJCT-ND, TempCo="200 ppm/C", Tolerance_%=5, Value1=5%, Value2=0.063W, Value_Code=100k
R39 R48 R49: "RES, 100, 1%, 0.1 W, 0402", Manufacturer=Panasonic, Power_W=0.1, Supplier Part Number 1=P100LCT-ND, TempCo="100 ppm/C", Tolerance_%=1, Value1=1%, Value2=0.1W, Value_Code=100R, ValueDisplayed=100
R40 R42 R44 R45: "RES, 750, 5%, 0.1 W, 0603", Manufacturer="Yageo America", Power_W=0.1, Supplier Part Number 1=311-750GRCT-ND, TempCo="100 ppm/C", Tolerance_%=5, Value1=5%, Value2=0.1W, Value_Code=750R, ValueDisplayed=750
R43 R46 R47: "RES, 10 k, 5%, 0.063 W, 0402", Manufacturer=Vishay-Dale, Power_W=0.063, Supplier Part Number 1=541-10KJCT-ND, TempCo="200 ppm/C", Tolerance_%=5, Value1=5%, Value2=0.063W, Value_Code=10k0, ValueDisplayed=10k
SW1: "Switch, Tactile, SPST-NO, SMT", CurrentRating_mA=50, Manufacturer=Panasonic, Supplier Part Number 1=P8088SCT-ND
SW2 SW3: "Switch, SPST-NO, Off-Mom, 1 Pos, 0.05A, 12VDC, TH", CurrentRating_mA=50, Manufacturer=APEM, Supplier Part Number 1=679-2400-ND
TP1: "Test Point, Miniature, SMT", Manufacturer=Keystone, Supplier Part Number 1=36-5015TR-ND
U1: library part CC3120MODRNMMOBR, "SimpleLink Certified Wi-Fi Network Processor Internet-of-Things Module Solution for MCU Applications, MOB0063A (QFM-63)", Alternate Manufacturer="Texas Instruments"
U2: "Ultralow-Noise, High PSRR, Fast, RF, 1-A Low-Dropout Linear Regulators, DCQ0006A (SOT-6)", Alternate Manufacturer="Texas Instruments"
ZZ2: library part CMP-0077236-1
ZZ3: library part CMP-0077237-1
ZZ4: library part CMP-0077238-1

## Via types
v1: diameter 19.68, hole 7.87, Top Layer to Bottom Layer, tented both sides, 240 vias
v2: diameter 19.68, hole 7.87, Top Layer to Bottom Layer, 40 vias
v3: diameter 30, hole 20, Top Layer to Bottom Layer, tented both sides, 19 vias
v4: diameter 20, hole 10, Top Layer to Bottom Layer, tented both sides, 4 vias
v5: diameter 24, hole 10, Top Layer to Bottom Layer, tented both sides, 2 vias

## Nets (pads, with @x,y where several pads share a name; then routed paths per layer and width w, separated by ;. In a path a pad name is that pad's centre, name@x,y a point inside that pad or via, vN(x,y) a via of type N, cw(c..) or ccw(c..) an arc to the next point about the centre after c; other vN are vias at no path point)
CC_IRQ: R4.1 R18.2 U1.11 | length 808.9
  Top Layer w6: U1.11@1283.6,781.57 1283.6,807.1 v1(1299.5,823) ; v1(1624.3,939.6) 1664.48,939.6 R18.2@1665.38,940.5 ; R4.1@1709.12,1224.2 1709.12,1199.7 1738.5,1170.32 v1(1738.5,1154.7)
  Bottom Layer w6: v1(1299.5,823) 1299.5,826.8 1387.6,914.9 1599.6,914.9 v1(1624.3,939.6) 1670.9,986.2 1670.9,1087.1 v1(1738.5,1154.7)
CC_NHIB: R15.1 R25.1 R47.1 SW3.2 U1.4 | length 1860.7
  Top Layer w6: SW3.2@91.86,105.44 149.42,163 154.55,163 R47.1@289.58,163 ; R25.1@522.52,750.8 557.6,750.8 586.49,750.8 v1(601.7,735.59) 692.71,735.59 702.9,725.4 918,725.4 933.6,741 933.6,751.8 ; v1(606.1,165.4) 606.1,337.43 671.8,403.13 671.8,565.72 R15.1@665.82,571.7 665.82,584.48 v1(649.6,600.7) ; 933.6,763.3 933.6,751.8 ; U1.4@933.6,781.57 933.6,751.8
  Bottom Layer w6: SW3.2@96.99,105.44 156.95,165.4 v1(606.1,165.4) ; v1(601.7,735.59) 601.7,645.2 v1@646.2,600.7
CC_NRESET: D2.2 R46.1 SW2.2 U1.35 | length 1224.1
  Top Layer w6: v1(1184.9,1297.7) U1.35@1184.9,1418.83 ; v1(1607.7,1288.9) 1681.6,1288.9 1724.8,1245.7 1786.9,1245.7 1800.99,1259.79 1800.99,1299.79 1845.8,1344.6 1845.8,1435.1 1811.7,1469.2 1811.7,1560.5 1853.98,1602.78 1859.11,1607.91 SW2.2@1912.12,1607.91
  Top Layer w10: U1.35@1181.8,1421.93 U1.35@1184.9,1418.83 ; R46.1@1801.12,1269.2 R46.1@1802.32,1270.4
  Bottom Layer w6: v1(1184.9,1297.7) 1550.8,1297.7 1559.6,1288.9 v1(1607.7,1288.9)
CC_NWP_UART_TX: R27.1 U1.52 | length 1293.6
  Top Layer w6: U1.52@782.62,948.5 783.12,948 v1(822.5,948)
  Top Layer w8: v1(1698.7,635.1) 1728.3,635.1 1751.2,658 R27.1@1790.38,658
  Bottom Layer w6: v1(822.5,948) 822.5,735.3 949.3,608.5 1090.6,608.5 1116.98,634.88 1269.02,634.88 1633.48,635.1 v1(1698.7,635.1)
CC_SPI_CLK: R29.1 U1.5 | length 519.9
  Top Layer w6: R29.1@518.02,699.7 929.3,699.7 984.3,754.7 U1.5@984.3,785.57
CC_SPI_CS: R19.2 U1.8 | length 621.3
  Top Layer w10: U1.8@1133.6,781.57 1184.67,730.5 v1(1246.6,730.5) ; v1(1594.9,862) 1622.2,889.3 1664.18,889.3 R19.2@1665.38,890.5
  Bottom Layer w10: v1(1246.6,730.5) 1308.7,730.5 1440.2,862 v1@1597,862
CC_SPI_DIN: R26.2 U1.6 | length 1039.8
  Top Layer w6: U1.6@1033.6,781.57 1033.6,719.9 1345.8,407.7 1649.3,407.7 1715.4,473.8 1715.4,513.7 1772.4,570.7 R26.2@1791.48,570.7
CC_SPI_DOUT: R3.1 R28.2 U1.7 | length 1011.8
  Top Layer w6: U1.7@1084.3,785.57 1084.3,742.1 1151.38,675.02 R3.1@1151.38,656.8 1153.2,654.98 1153.2,626.6 1350.3,429.5 1629.2,429.5 1692.1,492.4 1692.1,537.5 1772.4,617.8 R28.2@1791.48,617.8
CC_UART1_CTS: R21.1 U1.51 | length 1219.4
  Top Layer w6: U1.51@782.62,998.5 833.7,998.5 865.3,966.9 v1(896.6,966.9) ; v1(1623.5,840.3) R21.1@1665.18,840.3
  Top Layer w10: U1.51@783.32,1002.5 U1.51@785.92,999.9 ; R21.1@1665.18,840.3 R21.1@1665.38,840.5
  Bottom Layer w6: v1(896.6,966.9) 896.6,752 979.1,669.5 1028.6,669.5 1069.7,710.6 1314.3,710.6 1444,840.3 v1(1623.5,840.3)
CC_UART1_RTS: R10.1 R23.1 U1.44 | length 1058
  Top Layer w6: U1.44@782.62,1348.5 826.5,1348.5 845.7,1329.3 v1(845.7,1260.1) ; v1(1581.8,1199) 1596.98,1199 R10.1@1666.08,1129.9 1665.38,1129.2 R23.1@1665.38,1085.5 ; R23.1@1664.58,1085.5 R23.1@1664.98,1085.1
  Top Layer w10: U1.44@782.42,1351.6 U1.44@783.32,1352.5
  Bottom Layer w6: v1(845.7,1260.1) 1287.3,1260.1 1329,1218.4 1569.8,1218.4 v1@1581.8,1206.4
CC_UART1_RX: R6.2 R22.1 U1.47 | length 644.2
  Top Layer w6: R22.1@521.52,800.8 535.62,814.9 R6.2@573.68,814.9 ; R22.1@532.82,789.5 654.7,789.5 753.6,888.4 753.6,1177.48 U1.47@778.62,1202.5
CC_UART1_TX: R5.2 R20.1 U1.46 | length 641.6
  Top Layer w6: R20.1@521.52,850.8 R5.2@560.9,850.8 ; R20.1@521.52,862.52 542.4,883.4 700.4,883.4 741.6,924.6 741.6,1234 756.1,1248.5 U1.46@782.62,1248.5
CC_WL_UART_TX: R30.1 U1.50 | length 1366
  Top Layer w6: U1.50@782.62,1048.5 851.8,1048.5 v1(851.9,1048.6) ; v1(1737.4,714.6) 1737.5,714.5 R30.1@1791.48,714.5
  Bottom Layer w6: v1(851.9,1048.6) 851.9,1028.6 867.1,1013.4 867.1,753.8 970.2,650.7 1056,650.7 1086.1,680.8 1709.56,680.8 v1(1737.4,714.6)
CC_WLRS232_RX: R33.1 U1.49 | length 1546.5
  Top Layer w6: U1.49@782.62,1098.5 804.2,1098.5 822.5,1080.2 v1(822.5,1077.8) ; v1(1764.9,485.4) R33.1@1791.48,485.4
  Bottom Layer w6: v1(822.5,1077.8) 822.5,1028.6 849.2,1001.9 849.2,737.4 958.2,628.4 1076.7,628.4 1107.2,658.9 1716.5,658.9 1741.7,633.7 1741.7,508.6 v1(1764.9,485.4)
CC_WLRS232_TX: R32.1 U1.48 | length 1409.9
  Top Layer w6: U1.48@782.62,1148.5 795.4,1148.5 v1(814.2,1129.7) ; v1(1115.1,582.7) 1317.8,380 R32.1@1616.38,380
  Bottom Layer w6: v1(814.2,1129.7) 814.2,1110.6 803.4,1099.8 803.4,715.6 936.3,582.7 v1(1115.1,582.7)
GND: C1.2 C2.2 C3.2 C6.1 C6.2 C7.1 C9.2 C10.2 C11.2 C12.2 C13.2 C14.2 D5.1 E1.1 E1.2 J1.1 J1.9 J2.2@1563.9,1665.37 J2.3@1563.9,1549.23 L1.2 L5.1 P2.1 P3.2 Q1.2 Q2.2 Q3.2 R3.2 R4.2 R10.2 R11.2 R12.2 R13.2 R14.1 R37.1 R38.2 R48.1 R49.1 TP1.1 U1.1 U1.2 U1.16 U1.25 U1.26 U1.27 U1.28 U1.29 U1.30 U1.32 U1.38 U1.43 U1.55@981.43,921.33 U1.56@1099.54,921.33 U1.57@1217.66,921.33 U1.58@981.43,1039.44 U1.59@1099.54,1039.44 U1.60@1217.66,1039.44 U1.61@981.43,1157.56 U1.62@1099.54,1157.56 U1.63@1217.66,1157.56 U2.3 U2.6@1197.89,165 | length 1477.6
  Top Layer w6: 716.7,441.8 730.2,455.3 C1.2@736.58,455.3 721.07,439.79 C11.2@721.07,382 ; R14.1@1590.2,992.48 1607.18,992.48 v1(1624,1009.3)
  Top Layer w10: U2.6@1197.89,165 1197.89,80.31 v3(1207,71.2) ; U2.3@1434.11,165 C13.2@1523,165 1565.53,165 1597.83,197.3 1638.3,197.3 C9.2@1711,270 ; v1(1685.5,1174.8) 1691.2,1174.8 1713.32,1152.68 R10.2@1713.32,1129.9 ; P2.1@2050,1350 2176.2,1350 2207.08,1380.88 R49.1@2207.08,1423.66
  Top Layer w25: 1188.13,1579.15 E1.2@1115.16,1579.15 E1.1@1115.16,1657.89 1128.74,1644.31 C6.1@1179.6,1644.31 1183.19,1647.9 C7.1@1233,1647.9
  Bottom Layer w6: v3(388.2,344.6) 471,261.8 v1(553.1,261.8)
  Bottom Layer w10: v1(553.1,261.8) v1@657.1,261.8 ; 1163,115.9 v3@1206.4,72.5
  other v1: 2018.3,23.86 601.3,24.56 84.6,26.06 1508.8,26.06 2156.5,27.2 1296,29 317.2,31.46 1358.5,30.6 492.7,34.46 1240.8,33.9 1172,35.8 2093.5,51.96 1271.6,61.4 344.6,67.06 277,68.66 619.5,70.86 573.2,74.66 1168.8,83.3 1238.3,82.6 1296,88.5 494.2,91.46 288.4,109.66 1254.8,111.1 477.1,118.9 1140.7,126.2 1254.8,148.2 1254.3,182 1139.7,201.3 77.8,211 1139.7,231.3 658.2,260.7 196.2,267.6 1780.5,272 145.4,274.5 1324.1,282.8 1755.4,292.1 1325.6,343.7 1541,357.7 542.7,378 2139.9,389.1 2232.2,405.36 1246.3,414.9 647.5,424.7 1193.9,427.7 34.1,429.86 2181.1,430.26 2258.8,445.76 124.5,448.9 1389.6,463.8 76.5,467.26 1150.1,472.1 2167.8,482.66 1345.8,490.5 2249.4,490.36 29.3,494.96 130.8,506.5 71,546 35.3,570.1 2158.7,590.36 41.7,632.5 138.3,702.7 2165.6,705.76 1705.2,724.4 51.1,747.5 1630,755.9 2154.8,772.96 2230.6,785.96 138.4,791.5 51.9,836.1 1365.1,837.6 138.6,851 2176.4,859.66 1400,878.4 52.7,919 2237.1,920.26 1420.9,949.3 1483.7,952.8 2163.4,974.46 141,987.5 2241.4,987.46 51.9,1012.9 1483.5,1014.4 2141.8,1032.96 140,1045.9 2243.6,1050.26 52.7,1085 1625.5,1100.2 2152.6,1104.46 2221.9,1143.46 138.1,1143.7 49.3,1151.6 2193.8,1193.36 51.6,1202.4 129.3,1205 1765.3,1206.7 2252.3,1214.96 2141.8,1217.16 1453.8,1255.3 1355.3,1259.9 50.6,1264.9 2182.9,1295.16 1438,1319.7 1344.1,1321 2263.1,1321.16 432.7,1344.1 1629.2,1349.9 2215,1362.5 498.2,1368.7 1709.9,1378 435.2,1384.5 1338.5,1384.6 1426.6,1385.8 567.7,1389.2 2146.6,1390 2263.1,1418.66 1933.6,1425.6 2027.9,1428.7 636.6,1436 203.6,1445.9 1035.6,1447.4 783.82,1447.6 1532.7,1450.8 1236.4,1458.1 715.6,1458.7 1353.2,1459.9 826.5,1461.1 673.5,1462.16 913.2,1463.2 1084.6,1462.9 994.7,1465.2 1419,1465 1478.6,1467.1 1772.9,1467.9 2258.4,1469.3 1179,1469.83 616.9,1476.5 1308.9,1481 784.7,1482.2 1129.1,1482.2 865,1483.1 954.96,1483.4 1038.6,1482.8 2221.9,1485.86 1260.8,1499 728.2,1504.7 1553.1,1505.6 1353.8,1507.46 661.7,1508.7 1602.5,1511.1 1503.5,1513.2 2267.4,1516.16 1180.5,1517.4 1219,1517.7 1418.1,1520.7 1969.7,1521.5 1462,1521.9 2018.8,1522.2 625,1523.4 1309.2,1530.3 28.2,1540 683.7,1543.2 773.6,1543.2 1622,1546.2 1352.2,1552.6 204.2,1555.7 1238.9,1562.5 1506.8,1562.8 1180.2,1568.9 1462.3,1573.9 1286.1,1574.8 1417.8,1576.6 727,1578.1 1335.1,1585.6 1205.2,1596.9 663.2,1597.7 1624.4,1601.9 1998,1606.4 1309.6,1608.6 773.3,1610.9 1232.6,1617.5 1273.2,1616.9 622.9,1622.9 1420.5,1642.2 727,1644.6 1472.5,1653.9 2260.9,1654.86 1622.9,1665.66 2206.8,1665.66 662.9,1675.3 42.9,1675.7 472.4,1676.26 773.3,1675.9 1498.7,1676.5 1185.3,1677.7 1233.5,1677.7 1276.2,1677.7 1322.8,1677.7 1357.7,1678 1417.5,1677.7
  other v2: 1197.89,111.85 1167.38,165 1228.4,165 1197.89,218.15 981.43,895.74 1099.54,895.74 1217.66,895.74 1125.14,920.35 955.84,921.33 1007.03,921.33 1073.95,921.33 1192.06,921.33 1243.25,921.33 981.43,946.93 1099.54,946.93 1217.66,946.93 981.43,1013.85 1099.54,1013.85 1217.66,1013.85 1125.14,1038.46 955.84,1039.44 1007.03,1039.44 1073.95,1039.44 1192.06,1039.44 1243.25,1039.44 981.43,1065.04 1099.54,1065.04 1217.66,1065.04 981.43,1131.96 1099.54,1131.96 1217.66,1131.96 955.84,1157.56 1007.03,1157.56 1073.95,1157.56 1125.14,1157.56 1192.06,1157.56 1243.25,1157.56 981.43,1183.15 1099.54,1183.15 1217.66,1183.15
  other v3: 992,210.9
MCU_RESET_IN: R1.2 R24.2 R34.2 R41.2 | length 1254.8
  Top Layer w6: R24.2@1748.38,338 1748.38,404.58 1761.9,418.1 1796.67,418.1 ; R34.2@1790.38,388 1790.38,411.81 1796.67,418.1 ; R41.2@1802,1397.3 1802,1371 v1(1806.6,1366.4) ; v1(1835.9,788) 1835.9,763.62 R1.2@1838.72,760.8 ; v1(1854.1,418.1) 1796.67,418.1
  Bottom Layer w6: v1(1806.6,1366.4) 1806.6,1313.7 1788.8,1295.9 1788.8,868.9 1835.9,821.8 v1(1835.9,788) 1854.4,769.5 1854.4,461.4 1854.1,461.1 v1(1854.1,418.1)
NetC2_1: C2.1 C3.1 J4.2 L2.1 L3.1 U1.37 U1.40 | length 578.7
  Top Layer w6: 761.6,1386.1 764.22,1383.48
  Top Layer w15: 764.22,1383.48 933.6,1383.48
  Top Layer w22: L2.1@571.6,1046.32 586.8,1061.52 ; J4.2@586.8,1155.2 586.8,1061.52 ; L3.1@615,1046.32 602,1046.32 586.8,1061.52 ; C2.1@715.5,1359.2 735.74,1379.44 ; U1.40@933.6,1415.43 933.6,1383.48 960.9,1364.6 1064.3,1364.6 1083.6,1383.9 U1.37@1083.6,1415.43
